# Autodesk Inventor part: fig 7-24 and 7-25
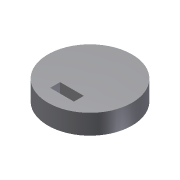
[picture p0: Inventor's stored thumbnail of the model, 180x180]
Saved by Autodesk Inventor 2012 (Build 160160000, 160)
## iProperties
Created: 2005-04
Part Number: fig 7-24 and 7-25
Document SubType Name: Modeling
Designer: CADCIM
Density: 1 g/cm^3
Material: Default
Author: CADCIM
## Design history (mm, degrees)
sketch "Sketch1"
  geometry: C1 r 21.205 at (0, 0)
  constraints: 1 centre point
extrude "Extrusion1" new body sketch "Sketch1" distance "d0" = 10; taper "d1" = 0 deg
sketch "Sketch2"
  geometry: L1 (-6, -9.113)-(6, -9.113); L2 (6, -9.113)-(6, -14.113); L3 (6, -14.113)-(-6, -14.113); L4 (-6, -14.113)-(-6, -9.113); C1 r 21.205 at (0, 0) reference
  constraints: 8 end point, 2 parallel, 1 horizontal, 1 perpendicular
  dimensions: "d2" = 6 distance from line of C1.centre L4; "d3" = 12 distance of L1.start L1.end; "d4" = 5 distance of L3.end L1.start
extrude "Extrusion2" cut sketch "Sketch2" stored distance "d5" = 10; taper "d6" = 0 deg
sketch "Sketch3"
  geometry: L1 (7.403, 8.063)-(-0.088, 16.951); L2 (-0.088, 16.951)-(-7.579, 8.063); A1 r 11.927 centre (-0.088, 17.344) between (-7.579, 8.063) and (7.403, 8.063)
  constraints: 4 end point, 2 point on circle, 1 centre point
extrude "Extrusion3" cut sketch "Sketch3" distance "d7" = 10; taper "d8" = 0 deg
body "Solid1"
